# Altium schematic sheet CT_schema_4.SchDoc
size 255 x 245 mm
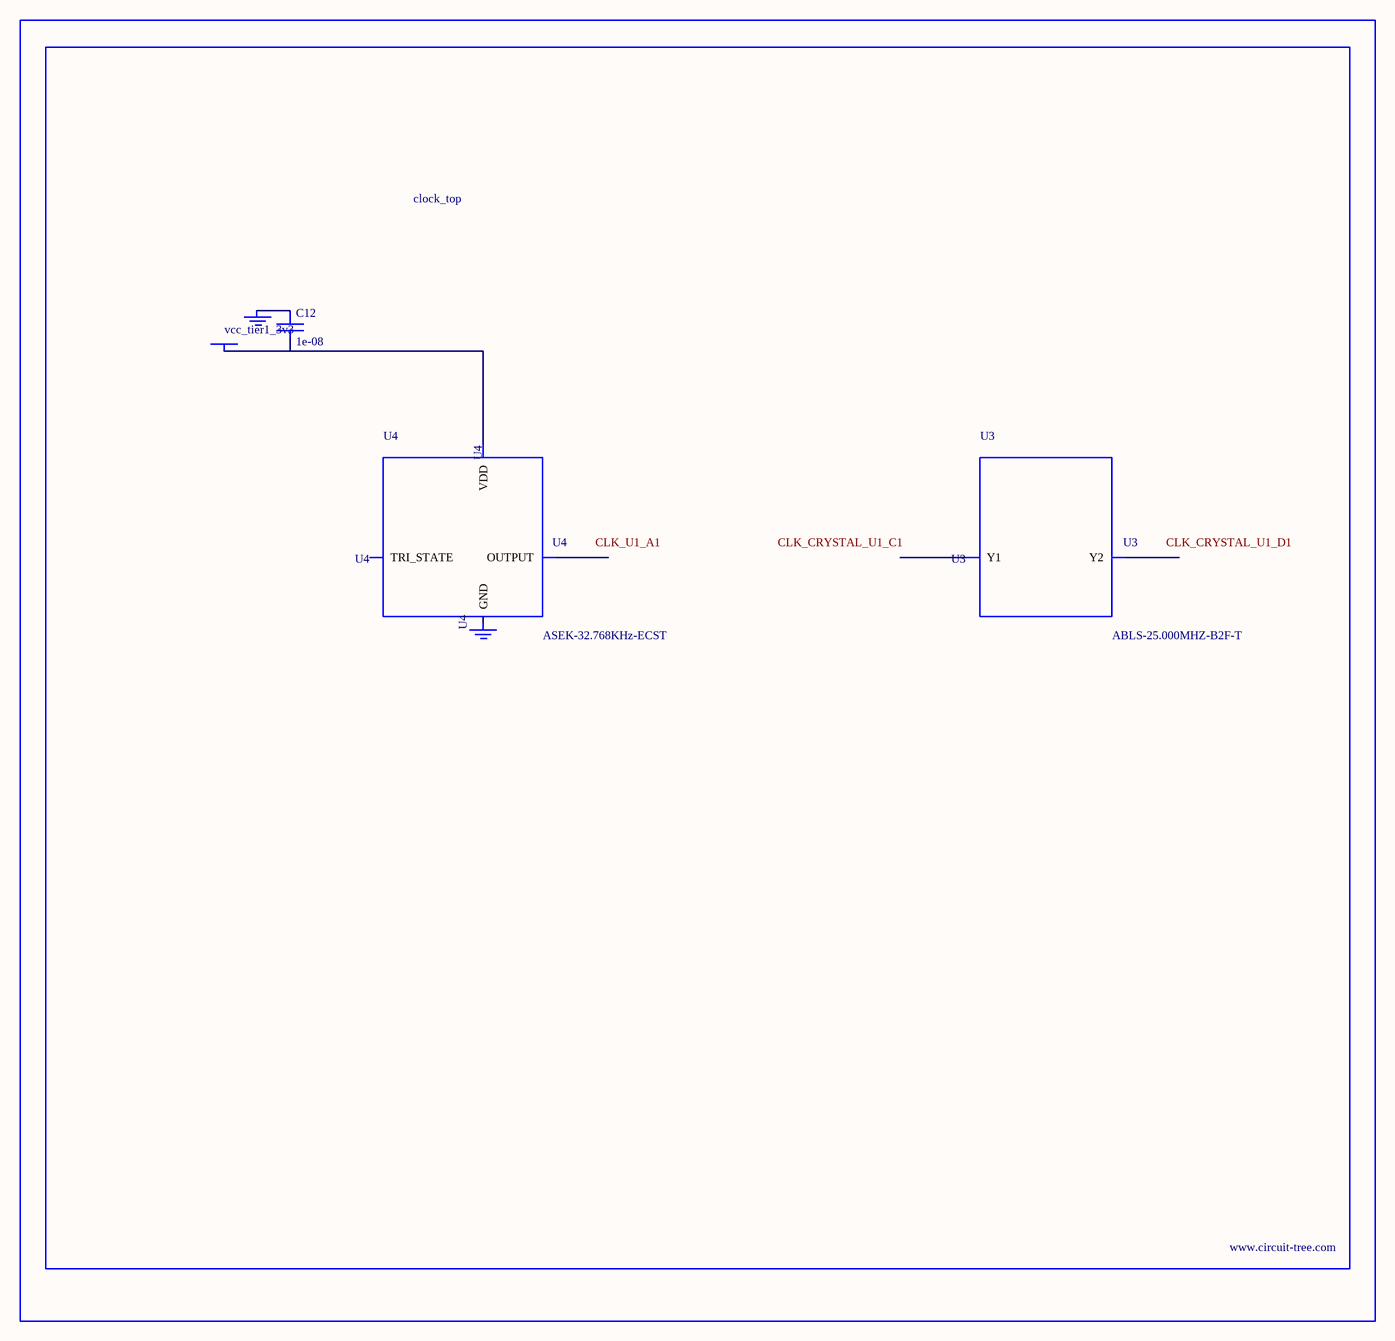
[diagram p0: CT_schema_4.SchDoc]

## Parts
BORDER3  (no value)
C12  1e-08  [C0402]
GND_INSTANCE_3_0  (no value)
GND_INSTANCE_3_1  (no value)
POWER_INSTANCE_3_0  vcc_tier1_3v3
U3  ABLS-25.000MHZ-B2F-T  [ABLS-25.000MHZ-B2F-T]
U4  ASEK-32.768KHz-ECST  [ASEK]

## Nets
NetC12_1: C12.1 GND_INSTANCE_3_0.0(GND)
NetC12_2: C12.2 POWER_INSTANCE_3_0.0(PWR) U4.4(VDD)

Not connected (* = marked no-connect by the designer): GND_INSTANCE_3_1 0(GND); U3 1(Y1) 2(Y2); U4 1(TRI_STATE) 2(GND) 3(OUTPUT)

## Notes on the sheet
- Labels drawn without touching a wire or pin: CLK_CRYSTAL_U1_C1, CLK_CRYSTAL_U1_D1, CLK_U1_A1

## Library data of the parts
BORDER3 = BORDER_PAGE3
C12 = C0402C103K3RAC
GND_INSTANCE_3_0 GND_INSTANCE_3_1 = GND
POWER_INSTANCE_3_0 = PWR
